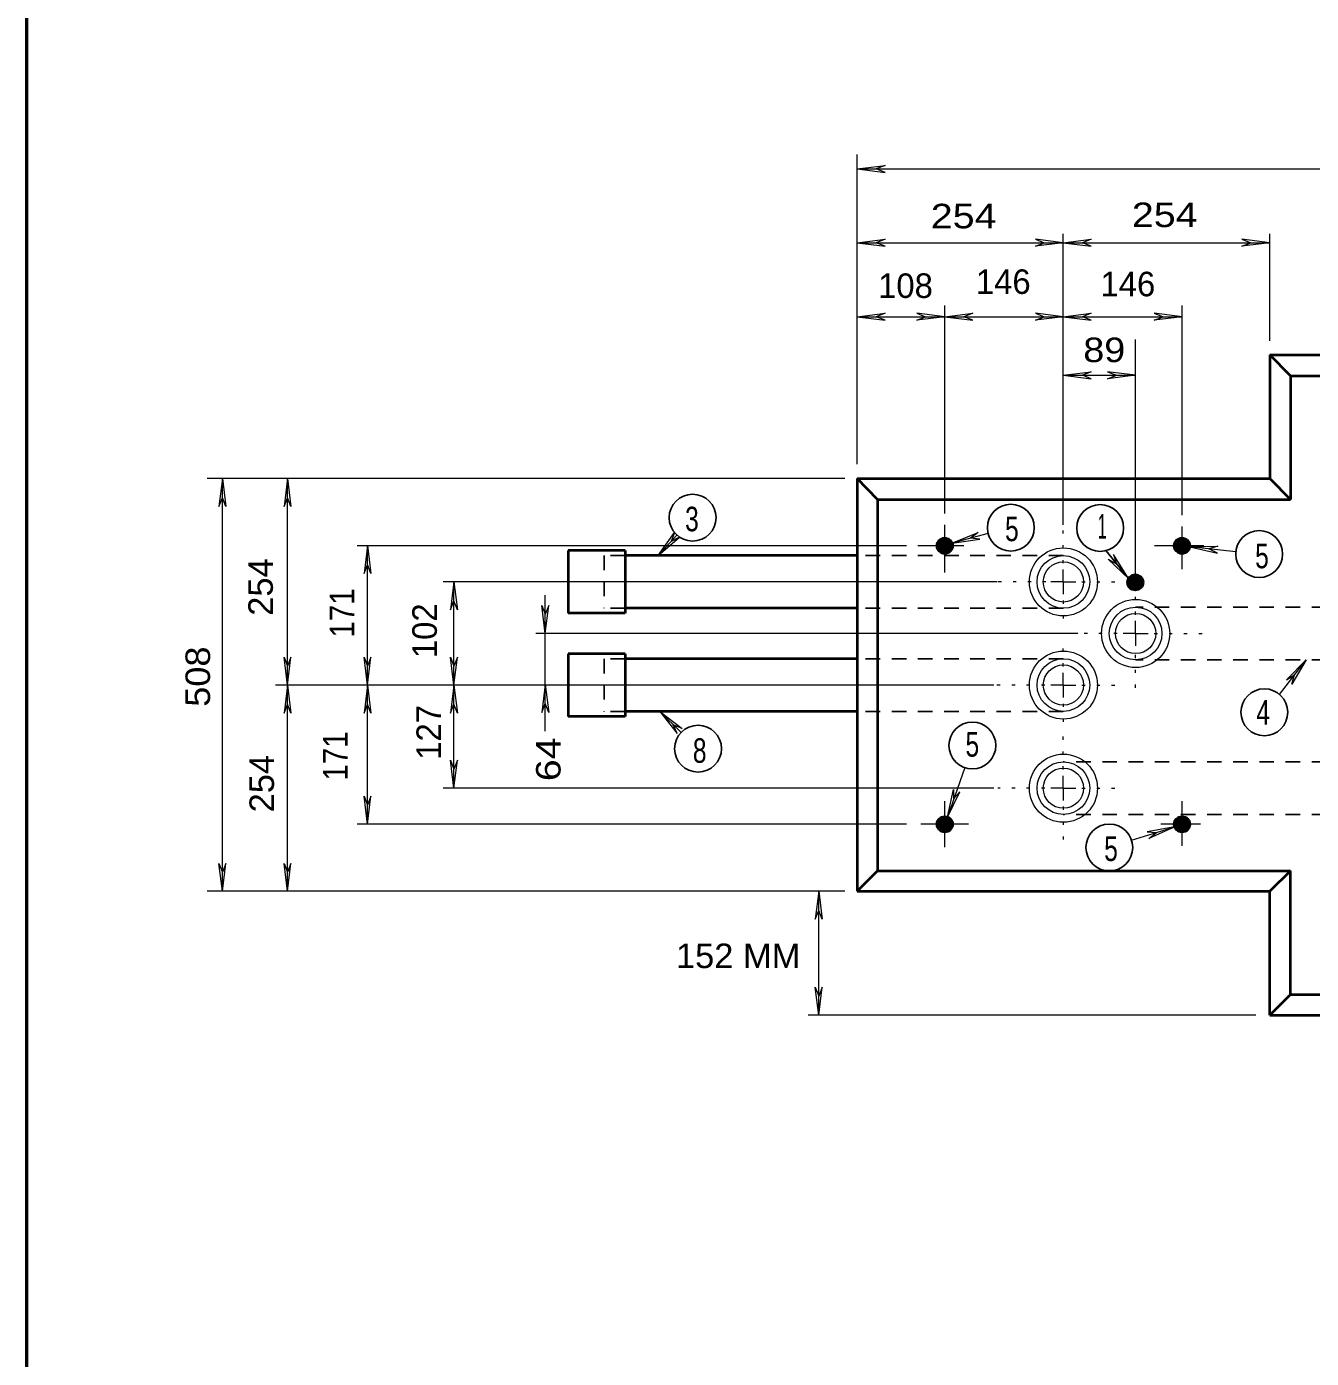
# Model space of a CAD drawing. Extents: x 312583 to 312854, y 144419 to 144597.
# Drawn here: x 312708.18 to 312747.96, y 144462.59 to 144503.84 of the extents above; entities that cross this region are included whole.
import ezdxf

# ---------------------------------------------------------------- set-up
doc = ezdxf.new("R2010")
doc.units = 0
doc.header["$LTSCALE"] = 0.3
doc.linetypes.add('DOTTED', pattern=[1.5, 0.3, -1.2])
doc.linetypes.add('SHORT_DASHED', pattern=[2.7, 1.5, -1.2])
doc.layers.add('1', color=7, linetype='Continuous', lineweight=25)
doc.layers.add('2', color=7, linetype='Continuous', lineweight=13)

msp = doc.modelspace()

# ---------------------------------------------------------------- linework, layer by layer
at = {"layer": '1', "lineweight": 40}
for p, q in [((312746.6716, 144493.6692), (312778.611, 144493.6692)), ((312746.6716, 144493.6692), (312746.6716, 144489.8358)), ((312747.308, 144493.0252), (312746.6716, 144493.6692)), ((312747.308, 144493.0252), (312777.9746, 144493.0252)), ((312747.308, 144493.0252), (312747.308, 144489.1918)), ((312733.8913, 144489.8358), (312733.8913, 144477.0555)), ((312733.8913, 144489.8358), (312746.6716, 144489.8358)), ((312734.5276, 144489.1918), (312733.8913, 144489.8358)), ((312746.6716, 144489.8358), (312747.308, 144489.1918)), ((312734.5276, 144489.1918), (312734.5276, 144477.6918)), ((312734.5276, 144489.1918), (312747.308, 144489.1918)), ((312726.7076, 144487.6125), (312724.9443, 144487.6125)), ((312724.9443, 144487.6125), (312724.9443, 144485.6652)), ((312726.7076, 144487.6125), (312726.7076, 144485.6652)), ((312733.8913, 144487.4515), (312726.7076, 144487.4515)), ((312726.7076, 144485.6652), (312724.9443, 144485.6652)), ((312733.8913, 144485.8262), (312726.7076, 144485.8262)), ((312726.7076, 144484.4155), (312724.9443, 144484.4155)), ((312724.9443, 144484.4155), (312724.9443, 144482.4682)), ((312726.7076, 144484.4155), (312726.7076, 144482.4682)), ((312733.8913, 144484.2545), (312726.7076, 144484.2545)), ((312726.7076, 144482.4682), (312724.9443, 144482.4682)), ((312733.8913, 144482.6292), (312726.7076, 144482.6292)), ((312733.8913, 144477.0555), (312734.5276, 144477.6918)), ((312734.5276, 144477.6918), (312747.308, 144477.6918)), ((312747.308, 144477.6918), (312746.6716, 144477.0555)), ((312747.308, 144473.8585), (312747.308, 144477.6918)), ((312733.8913, 144477.0555), (312746.6716, 144477.0555)), ((312746.6716, 144473.2222), (312746.6716, 144477.0555)), ((312747.308, 144473.8585), (312746.6716, 144473.2222)), ((312747.308, 144473.8585), (312777.9746, 144473.8585)), ((312746.6716, 144473.2222), (312778.611, 144473.2222))]:
    msp.add_line(p, q, dxfattribs=at)
at = {"layer": '1', "linetype": 'SHORT_DASHED'}
for p, q in [((312726.0636, 144487.4515), (312726.0636, 144485.8262)), ((312726.7076, 144487.4515), (312726.0636, 144487.4515)), ((312740.2776, 144487.4515), (312733.8913, 144487.4515)), ((312726.7076, 144485.8262), (312726.0636, 144485.8262)), ((312740.2776, 144485.8262), (312733.8913, 144485.8262)), ((312752.4676, 144485.8568), (312742.5163, 144485.8568)), ((312726.0636, 144484.2545), (312726.0636, 144482.6292)), ((312726.7076, 144484.2545), (312726.0636, 144484.2545)), ((312740.2776, 144484.2545), (312733.8913, 144484.2545)), ((312752.4676, 144484.2238), (312742.5163, 144484.2238)), ((312726.7076, 144482.6292), (312726.0636, 144482.6292)), ((312740.2776, 144482.6292), (312733.8913, 144482.6292)), ((312752.4676, 144481.0652), (312740.2776, 144481.0652)), ((312752.4676, 144479.4322), (312740.2776, 144479.4322))]:
    msp.add_line(p, q, dxfattribs=at)
at = {"layer": '1', "lineweight": 40}
for centre, radius in [((312736.6066, 144487.7563), 0.2396), ((312736.6066, 144487.7563), 0.2156), ((312736.6066, 144487.7563), 0.1941), ((312736.6066, 144487.7563), 0.1747), ((312736.6066, 144487.7563), 0.1572), ((312736.6066, 144487.7563), 0.1415), ((312736.6066, 144487.7563), 0.1273), ((312736.6066, 144487.7563), 0.1146), ((312736.6066, 144487.7563), 0.1031), ((312736.6066, 144487.7563), 0.0928), ((312736.6066, 144487.7563), 0.0835), ((312736.6066, 144487.7563), 0.0752), ((312736.6066, 144487.7563), 0.0677), ((312736.6066, 144487.7563), 0.0609), ((312736.6066, 144487.7563), 0.0548), ((312743.9538, 144487.7563), 0.2396), ((312743.9538, 144487.7563), 0.2156), ((312743.9538, 144487.7563), 0.1941), ((312743.9538, 144487.7563), 0.1747), ((312743.9538, 144487.7563), 0.1572), ((312743.9538, 144487.7563), 0.1415), ((312743.9538, 144487.7563), 0.1273), ((312743.9538, 144487.7563), 0.1146), ((312743.9538, 144487.7563), 0.1031), ((312743.9538, 144487.7563), 0.0928), ((312743.9538, 144487.7563), 0.0835), ((312743.9538, 144487.7563), 0.0752), ((312743.9538, 144487.7563), 0.0677), ((312743.9538, 144487.7563), 0.0609), ((312743.9538, 144487.7563), 0.0548), ((312742.5061, 144486.6222), 0.2396), ((312742.5061, 144486.6222), 0.2156), ((312742.5061, 144486.6222), 0.1941), ((312742.5061, 144486.6222), 0.1747), ((312742.5061, 144486.6222), 0.1572), ((312742.5061, 144486.6222), 0.1415), ((312742.5061, 144486.6222), 0.1273), ((312742.5061, 144486.6222), 0.1146), ((312742.5061, 144486.6222), 0.1031), ((312742.5061, 144486.6222), 0.0928), ((312742.5061, 144486.6222), 0.0835), ((312742.5061, 144486.6222), 0.0752), ((312742.5061, 144486.6222), 0.0677), ((312742.5061, 144486.6222), 0.0609), ((312742.5061, 144486.6222), 0.0548), ((312736.6066, 144479.1313), 0.2396), ((312736.6066, 144479.1313), 0.2156), ((312736.6066, 144479.1313), 0.1941), ((312736.6066, 144479.1313), 0.1747), ((312736.6066, 144479.1313), 0.1572), ((312736.6066, 144479.1313), 0.1415), ((312736.6066, 144479.1313), 0.1273), ((312736.6066, 144479.1313), 0.1146), ((312736.6066, 144479.1313), 0.1031), ((312736.6066, 144479.1313), 0.0928), ((312736.6066, 144479.1313), 0.0835), ((312736.6066, 144479.1313), 0.0752), ((312736.6066, 144479.1313), 0.0677), ((312736.6066, 144479.1313), 0.0609), ((312736.6066, 144479.1313), 0.0548), ((312743.9538, 144479.1313), 0.2396), ((312743.9538, 144479.1313), 0.2156), ((312743.9538, 144479.1313), 0.1941), ((312743.9538, 144479.1313), 0.1747), ((312743.9538, 144479.1313), 0.1572), ((312743.9538, 144479.1313), 0.1415), ((312743.9538, 144479.1313), 0.1273), ((312743.9538, 144479.1313), 0.1146), ((312743.9538, 144479.1313), 0.1031), ((312743.9538, 144479.1313), 0.0928), ((312743.9538, 144479.1313), 0.0835), ((312743.9538, 144479.1313), 0.0752), ((312743.9538, 144479.1313), 0.0677), ((312743.9538, 144479.1313), 0.0609), ((312743.9538, 144479.1313), 0.0548)]:
    msp.add_circle(centre, radius, dxfattribs=at)
at = {"layer": '1', "lineweight": 13}
for centre, radius in [((312740.2802, 144486.6382), 1.0542), ((312740.2802, 144486.6382), 0.8146), ((312740.2802, 144486.6382), 0.6232), ((312742.5163, 144485.041), 1.0542), ((312742.5163, 144485.041), 0.8146), ((312742.5163, 144485.041), 0.6232), ((312740.2802, 144483.4438), 1.0542), ((312740.2802, 144483.4438), 0.8146), ((312740.2802, 144483.4438), 0.6232), ((312740.2802, 144480.2493), 1.0542), ((312740.2802, 144480.2493), 0.8146), ((312740.2802, 144480.2493), 0.6232)]:
    msp.add_circle(centre, radius, dxfattribs=at)
at = {"layer": '2', "lineweight": 53}
msp.add_line((312708.1809, 144585.0846), (312708.1809, 144423.0846), dxfattribs=at)
at = {"layer": '2'}
for p, q in [((312733.8913, 144490.2805), (312733.8913, 144499.8715)), ((312733.8913, 144499.4268), (312734.7576, 144499.5342)), ((312733.8913, 144499.4268), (312778.611, 144499.4268)), ((312733.8913, 144499.4268), (312734.7576, 144499.3195)), ((312734.7576, 144499.5342), (312734.4816, 144499.4268)), ((312734.7576, 144499.3195), (312734.4816, 144499.4268)), ((312733.8913, 144497.1422), (312734.7576, 144497.2495)), ((312734.7576, 144497.2495), (312734.4816, 144497.1422)), ((312739.4113, 144497.2495), (312739.6873, 144497.1422)), ((312740.2776, 144497.1422), (312739.4113, 144497.2495)), ((312740.2776, 144488.4022), (312740.2776, 144497.4182)), ((312740.2776, 144497.1422), (312741.144, 144497.2495)), ((312741.144, 144497.2495), (312740.868, 144497.1422)), ((312745.8053, 144497.2495), (312746.0813, 144497.1422)), ((312746.6716, 144497.1422), (312745.8053, 144497.2495)), ((312746.6716, 144494.1062), (312746.6716, 144497.4182)), ((312733.8913, 144497.1422), (312734.7576, 144497.0348)), ((312734.7576, 144497.0348), (312734.4816, 144497.1422)), ((312739.4113, 144497.0348), (312739.6873, 144497.1422)), ((312740.2776, 144497.1422), (312739.4113, 144497.0348)), ((312740.2776, 144497.1422), (312741.144, 144497.0348)), ((312741.144, 144497.0348), (312740.868, 144497.1422)), ((312745.8053, 144497.0348), (312746.0813, 144497.1422)), ((312746.6716, 144497.1422), (312745.8053, 144497.0348)), ((312736.6053, 144488.7548), (312736.6053, 144495.2025)), ((312743.9576, 144488.7012), (312743.9576, 144495.2025)), ((312733.8913, 144494.8498), (312734.7576, 144494.9572)), ((312733.8913, 144494.8498), (312734.7576, 144494.7425)), ((312734.7576, 144494.9572), (312734.4816, 144494.8498)), ((312734.7576, 144494.7425), (312734.4816, 144494.8498)), ((312735.739, 144494.9572), (312736.015, 144494.8498)), ((312736.6053, 144494.8498), (312735.739, 144494.9572)), ((312735.739, 144494.7425), (312736.015, 144494.8498)), ((312736.6053, 144494.8498), (312735.739, 144494.7425)), ((312736.6053, 144494.8498), (312737.4716, 144494.9572)), ((312736.6053, 144494.8498), (312737.4716, 144494.7425)), ((312737.4716, 144494.9572), (312737.1956, 144494.8498)), ((312737.4716, 144494.7425), (312737.1956, 144494.8498)), ((312739.4113, 144494.9572), (312739.6873, 144494.8498)), ((312740.2776, 144494.8498), (312739.4113, 144494.9572)), ((312739.4113, 144494.7425), (312739.6873, 144494.8498)), ((312740.2776, 144494.8498), (312739.4113, 144494.7425)), ((312740.2776, 144494.8498), (312741.144, 144494.9572)), ((312740.2776, 144494.8498), (312741.144, 144494.7425)), ((312741.144, 144494.9572), (312740.868, 144494.8498)), ((312741.144, 144494.7425), (312740.868, 144494.8498)), ((312743.0913, 144494.9572), (312743.3673, 144494.8498)), ((312743.9576, 144494.8498), (312743.0913, 144494.9572)), ((312743.0913, 144494.7425), (312743.3673, 144494.8498)), ((312743.9576, 144494.8498), (312743.0913, 144494.7425)), ((312742.5163, 144486.8382), (312742.5163, 144494.1445)), ((312740.2776, 144493.0395), (312741.144, 144493.1468)), ((312741.144, 144493.1468), (312740.868, 144493.0395)), ((312741.65, 144493.1468), (312741.926, 144493.0395)), ((312742.5163, 144493.0395), (312741.65, 144493.1468)), ((312740.2776, 144493.0395), (312742.5163, 144493.0395)), ((312740.2776, 144493.0395), (312741.144, 144492.9321)), ((312741.144, 144492.9321), (312740.868, 144493.0395)), ((312741.65, 144492.9321), (312741.926, 144493.0395)), ((312742.5163, 144493.0395), (312741.65, 144492.9321)), ((312733.508, 144489.8358), (312713.774, 144489.8358)), ((312714.2416, 144489.8358), (312714.1343, 144488.9695)), ((312714.2416, 144477.0555), (312714.2416, 144489.8358)), ((312714.2416, 144489.8358), (312714.349, 144488.9695)), ((312716.258, 144489.8358), (312716.1506, 144488.9695)), ((312716.258, 144489.8358), (312716.3653, 144488.9695)), ((312714.1343, 144488.9695), (312714.2416, 144489.2455)), ((312714.349, 144488.9695), (312714.2416, 144489.2455)), ((312716.1506, 144488.9695), (312716.258, 144489.2455)), ((312716.3653, 144488.9695), (312716.258, 144489.2455)), ((312727.735, 144487.4515), (312728.241, 144488.1645)), ((312728.241, 144488.1645), (312728.1336, 144487.8885)), ((312736.6053, 144486.9302), (312736.6053, 144488.4098)), ((312736.8276, 144487.8425), (312737.6403, 144488.1645)), ((312737.947, 144488.1338), (312736.8276, 144487.8425)), ((312737.6403, 144488.1645), (312737.4026, 144487.9882)), ((312743.9576, 144487.0298), (312743.9576, 144488.3562)), ((312735.4246, 144487.7582), (312718.4123, 144487.7582)), ((312718.7343, 144487.7658), (312718.627, 144486.8995)), ((312718.7343, 144487.7658), (312718.8416, 144486.8995)), ((312728.31, 144488.0878), (312727.735, 144487.4515)), ((312727.735, 144487.4515), (312728.3943, 144488.0265)), ((312728.3943, 144488.0265), (312728.1336, 144487.8885)), ((312737.1956, 144487.7582), (312735.7696, 144487.7582)), ((312736.8276, 144487.8425), (312737.694, 144487.9575)), ((312737.694, 144487.9575), (312737.4026, 144487.9882)), ((312744.6246, 144487.7582), (312743.099, 144487.7582)), ((312744.1953, 144487.7275), (312745.0616, 144487.7428)), ((312745.6213, 144487.5742), (312744.1953, 144487.7275)), ((312744.1953, 144487.7275), (312745.0463, 144487.5282)), ((312745.0616, 144487.7428), (312744.778, 144487.6662)), ((312741.6653, 144487.3442), (312741.926, 144487.1985)), ((312742.294, 144486.7385), (312741.6653, 144487.3442)), ((312741.834, 144487.4822), (312741.926, 144487.1985)), ((312742.294, 144486.7385), (312741.834, 144487.4822)), ((312745.0463, 144487.5282), (312744.778, 144487.6662)), ((312718.627, 144486.8995), (312718.7343, 144487.1755)), ((312718.8416, 144486.8995), (312718.7343, 144487.1755)), ((312740.2776, 144486.6388), (312740.2776, 144487.0222)), ((312738.2306, 144486.6388), (312721.0803, 144486.6388)), ((312721.41, 144486.6388), (312721.3026, 144485.7725)), ((312721.41, 144486.6388), (312721.5173, 144485.7725)), ((312740.2776, 144486.6388), (312739.8943, 144486.6388)), ((312740.2776, 144486.6388), (312740.661, 144486.6388)), ((312740.2776, 144486.6388), (312740.2776, 144486.2555)), ((312721.3026, 144485.7725), (312721.41, 144486.0485)), ((312721.5173, 144485.7725), (312721.41, 144486.0485)), ((312724.239, 144482.0113), (312724.239, 144486.2325)), ((312724.1316, 144485.9105), (312724.239, 144485.6345)), ((312724.239, 144485.0442), (312724.1316, 144485.9105)), ((312724.3463, 144485.9105), (312724.239, 144485.6345)), ((312724.239, 144485.0442), (312724.3463, 144485.9105)), ((312742.5163, 144485.0442), (312742.5163, 144485.4275)), ((312740.7223, 144485.0442), (312723.9476, 144485.0442)), ((312742.5163, 144485.0442), (312742.133, 144485.0442)), ((312742.5163, 144485.0442), (312742.8996, 144485.0442)), ((312742.5163, 144485.0442), (312742.5163, 144484.6608)), ((312716.1506, 144484.3082), (312716.258, 144484.0322)), ((312716.258, 144483.4418), (312716.1506, 144484.3082)), ((312716.3653, 144484.3082), (312716.258, 144484.0322)), ((312716.258, 144483.4418), (312716.3653, 144484.3082)), ((312718.627, 144484.3082), (312718.7343, 144484.0322)), ((312718.7343, 144483.4418), (312718.627, 144484.3082)), ((312718.8416, 144484.3082), (312718.7343, 144484.0322)), ((312718.7343, 144483.4418), (312718.8416, 144484.3082)), ((312721.3026, 144484.3082), (312721.41, 144484.0322)), ((312721.41, 144483.4418), (312721.3026, 144484.3082)), ((312721.5173, 144484.3082), (312721.41, 144484.0322)), ((312721.41, 144483.4418), (312721.5173, 144484.3082)), ((312746.9706, 144483.1505), (312747.7986, 144484.2238)), ((312747.7986, 144484.2238), (312747.1853, 144483.6028)), ((312747.7986, 144484.2238), (312747.354, 144483.4725)), ((312740.2776, 144483.4418), (312740.2776, 144483.8252)), ((312747.1853, 144483.6028), (312747.4383, 144483.7562)), ((312747.354, 144483.4725), (312747.4383, 144483.7562)), ((312738.131, 144483.4418), (312715.89, 144483.4418)), ((312716.258, 144483.4418), (312716.1506, 144482.5755)), ((312716.258, 144483.4418), (312716.3653, 144482.5755)), ((312718.7343, 144483.4418), (312718.627, 144482.5755)), ((312718.7343, 144483.4418), (312718.8416, 144482.5755)), ((312721.41, 144483.4418), (312721.3026, 144482.5755)), ((312721.41, 144483.4418), (312721.5173, 144482.5755)), ((312724.239, 144483.4648), (312724.1316, 144482.5985)), ((312724.239, 144483.4648), (312724.3463, 144482.5985)), ((312740.2776, 144483.4418), (312739.8943, 144483.4418)), ((312740.2776, 144483.4418), (312740.661, 144483.4418)), ((312740.2776, 144483.4418), (312740.2776, 144483.0585)), ((312716.1506, 144482.5755), (312716.258, 144482.8515)), ((312716.3653, 144482.5755), (312716.258, 144482.8515)), ((312718.627, 144482.5755), (312718.7343, 144482.8515)), ((312718.8416, 144482.5755), (312718.7343, 144482.8515)), ((312721.3026, 144482.5755), (312721.41, 144482.8515)), ((312721.5173, 144482.5755), (312721.41, 144482.8515)), ((312724.1316, 144482.5985), (312724.239, 144482.8745)), ((312724.3463, 144482.5985), (312724.239, 144482.8745)), ((312728.448, 144481.9775), (312727.781, 144482.6292)), ((312727.781, 144482.6292), (312728.3253, 144481.9468)), ((312727.781, 144482.6292), (312728.4786, 144482.1002)), ((312728.3253, 144481.9468), (312728.2026, 144482.2152)), ((312728.4786, 144482.1002), (312728.2026, 144482.2152)), ((312721.3026, 144481.1188), (312721.41, 144480.8428)), ((312721.41, 144480.2525), (312721.3026, 144481.1188)), ((312721.5173, 144481.1188), (312721.41, 144480.8428)), ((312721.41, 144480.2525), (312721.5173, 144481.1188)), ((312737.2263, 144480.8888), (312736.6896, 144479.3555)), ((312740.2776, 144480.2525), (312740.2776, 144480.6358)), ((312718.627, 144479.9995), (312718.7343, 144479.7235)), ((312718.7343, 144479.1332), (312718.627, 144479.9995)), ((312718.8416, 144479.9995), (312718.7343, 144479.7235)), ((312718.7343, 144479.1332), (312718.8416, 144479.9995)), ((312738.131, 144480.2525), (312721.0803, 144480.2525)), ((312736.6896, 144479.3555), (312736.8736, 144480.2065)), ((312736.6896, 144479.3555), (312737.073, 144480.1375)), ((312736.8736, 144480.2065), (312736.8813, 144479.9152)), ((312737.073, 144480.1375), (312736.8813, 144479.9152)), ((312740.2776, 144480.2525), (312739.8943, 144480.2525)), ((312740.2776, 144480.2525), (312740.661, 144480.2525)), ((312740.2776, 144480.2525), (312740.2776, 144479.8692)), ((312736.6053, 144478.4202), (312736.6053, 144479.8462)), ((312743.9576, 144478.4662), (312743.9576, 144479.8462)), ((312735.4246, 144479.1332), (312718.4123, 144479.1332)), ((312737.3413, 144479.1332), (312735.8693, 144479.1332)), ((312742.3936, 144478.6348), (312743.7276, 144479.0565)), ((312743.7276, 144479.0565), (312742.869, 144478.8955)), ((312743.7276, 144479.0565), (312742.9303, 144478.6885)), ((312744.525, 144479.1332), (312743.2983, 144479.1332)), ((312742.869, 144478.8955), (312743.1603, 144478.8802)), ((312742.9303, 144478.6885), (312743.1603, 144478.8802)), ((312714.1343, 144477.9218), (312714.2416, 144477.6458)), ((312714.2416, 144477.0555), (312714.1343, 144477.9218)), ((312714.349, 144477.9218), (312714.2416, 144477.6458)), ((312714.2416, 144477.0555), (312714.349, 144477.9218)), ((312716.1506, 144477.9218), (312716.258, 144477.6458)), ((312716.258, 144477.0555), (312716.1506, 144477.9218)), ((312716.3653, 144477.9218), (312716.258, 144477.6458)), ((312716.258, 144477.0555), (312716.3653, 144477.9218)), ((312733.508, 144477.0555), (312713.774, 144477.0555)), ((312732.703, 144477.0555), (312732.5956, 144476.1892)), ((312732.703, 144473.2222), (312732.703, 144477.0555)), ((312732.703, 144477.0555), (312732.8103, 144476.1892)), ((312732.5956, 144476.1892), (312732.703, 144476.4652)), ((312732.8103, 144476.1892), (312732.703, 144476.4652)), ((312732.5956, 144474.0885), (312732.703, 144473.8125)), ((312732.703, 144473.2222), (312732.5956, 144474.0885)), ((312732.8103, 144474.0885), (312732.703, 144473.8125)), ((312732.703, 144473.2222), (312732.8103, 144474.0885)), ((312746.2346, 144473.2222), (312732.3733, 144473.2222))]:
    msp.add_line(p, q, dxfattribs=at)
at = {"layer": '2', "linetype": 'DOTTED'}
for p, q in [((312740.2776, 144487.2138), (312740.2776, 144488.4022)), ((312739.741, 144486.6388), (312738.2306, 144486.6388)), ((312740.8526, 144486.6388), (312742.0716, 144486.6388)), ((312742.5163, 144485.6192), (312742.5163, 144486.8382)), ((312740.2776, 144486.0638), (312740.2776, 144485.1898)), ((312740.2776, 144484.0168), (312740.2776, 144484.8448)), ((312741.9413, 144485.0442), (312740.7223, 144485.0442)), ((312743.0913, 144485.0442), (312744.594, 144485.0442)), ((312742.5163, 144483.3575), (312742.5163, 144484.6608)), ((312739.7026, 144483.4418), (312738.131, 144483.4418)), ((312740.8526, 144483.4418), (312742.0716, 144483.4418)), ((312740.2776, 144482.8668), (312740.2776, 144482.0235)), ((312740.2776, 144480.8275), (312740.2776, 144482.0235)), ((312739.7026, 144480.2525), (312738.2536, 144480.2525)), ((312740.8526, 144480.2525), (312742.1023, 144480.2525)), ((312740.2776, 144479.6775), (312740.2776, 144478.3818))]:
    msp.add_line(p, q, dxfattribs=at)
at = {"layer": '2', "lineweight": 25}
msp.add_line((312741.604, 144487.5972), (312742.294, 144486.7385), dxfattribs=at)
at = {"layer": '2'}
for points in [[(312733.8913, 144497.1422), (312740.2776, 144497.1422), (312746.6716, 144497.1422)], [(312733.8913, 144494.8498), (312736.6053, 144494.8498), (312740.2776, 144494.8498), (312743.9576, 144494.8498)], [(312716.258, 144477.0555), (312716.258, 144483.4418), (312716.258, 144489.8358)], [(312718.7343, 144479.1332), (312718.7343, 144483.4418), (312718.7343, 144487.7658)], [(312721.41, 144480.2525), (312721.41, 144483.4418), (312721.41, 144486.6388)]]:
    msp.add_lwpolyline(points, dxfattribs=at)
at = {"layer": '2', "lineweight": 25}
for centre in [(312728.7994, 144488.6277), (312738.6523, 144488.3166), (312741.418, 144488.3063), (312746.3432, 144487.5007), (312746.5017, 144482.6011), (312728.9687, 144481.4721), (312737.4627, 144481.5724), (312741.703, 144478.4119)]:
    msp.add_circle(centre, 0.7254, dxfattribs=at)

# ---------------------------------------------------------------- texts
at = {"layer": '2'}
for s, width, p in [('254 ', 1.2, (312736.1744, 144497.5885)), ('254 ', 1.2, (312742.3995, 144497.6274)), ('89 ', 1.15, (312740.8952, 144493.4454)), ('3', 0.75, (312728.5673, 144488.206)), ('5', 0.75, (312738.4728, 144487.8993)), ('1', 0.5, (312741.3414, 144487.9818)), ('5', 0.75, (312746.2164, 144487.061)), ('4', 0.75, (312746.2517, 144482.216)), ('5', 0.75, (312737.2486, 144481.2246)), ('8', 0.75, (312728.8077, 144481.035)), ('5', 0.75, (312741.5421, 144477.9941)), ('152 MM', 1.05, (312728.2824, 144474.6772))]:
    msp.add_text(s, height=0.76, dxfattribs=dict(at, width=width)).set_placement(p)
for s, p in [('108', (312734.5433, 144495.433)), ('146', (312737.5707, 144495.5577)), ('146', (312741.4277, 144495.4845))]:
    msp.add_text(s, height=0.76, dxfattribs=at).set_placement(p)
for s, width, p in [('254', 1.05, (312715.8037, 144485.5881)), ('171', 0.9, (312718.3273, 144484.9114)), ('508', 1.1, (312713.8591, 144482.7715)), ('171', 0.9, (312718.1166, 144480.4829)), ('64 ', 1.2, (312724.7121, 144480.4655)), ('254', 1.05, (312715.8396, 144479.4999))]:
    msp.add_text(s, height=0.76, rotation=90, dxfattribs=dict(at, width=width)).set_placement(p)
for s, p in [('102', (312720.8816, 144484.2774)), ('127', (312721.0093, 144481.1301))]:
    msp.add_text(s, height=0.76, rotation=90, dxfattribs=at).set_placement(p)

doc.saveas('drawing.dxf')
